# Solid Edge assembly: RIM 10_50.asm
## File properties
Title: Zylinder
Author: ahadarics
Template: iso metric assembly.asm
Last saved by: psaghy
Revision: 6
Application: Solid Edge
Username: ahadarics
Dokumentum tartalom típus: 1
Document Number: RIM 10/50
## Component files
Kit_2.par
Profilrohr.par
Kit_1.par
Kolbenstange.par
Mutter_1.par
Mutter_2.par
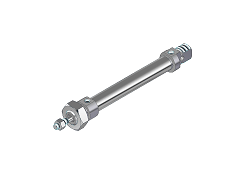
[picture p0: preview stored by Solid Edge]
